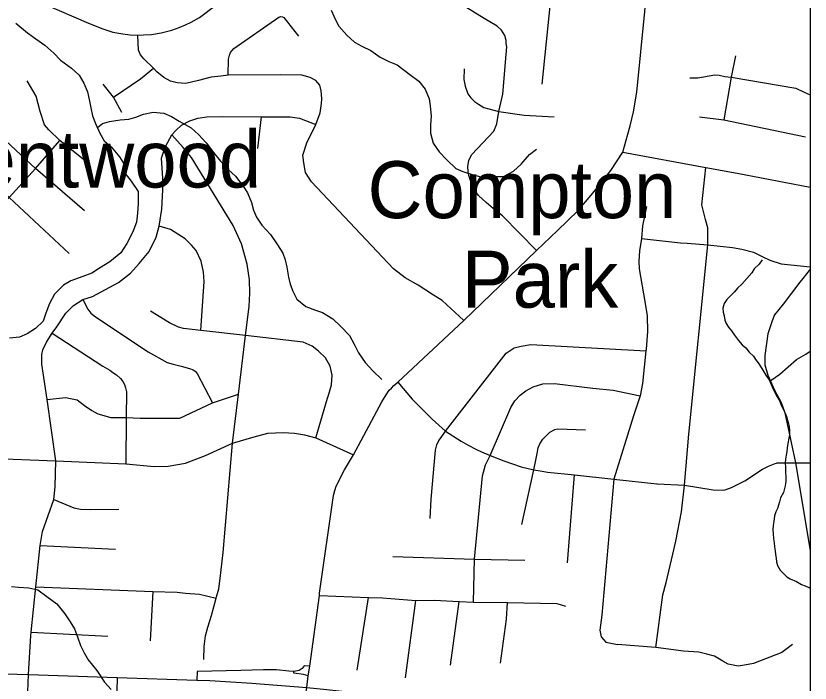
# Model space of a CAD drawing. Extents: x 0 to 69.5, y -4.5 to 22.
# Drawn here: x 7.698 to 8.8, y 15.277 to 16.203 of the extents above; entities that cross this region are included whole.
import ezdxf

# ---------------------------------------------------------------- set-up
doc = ezdxf.new("R2010")
doc.units = 0
for name, color, linetype in [('GM_X_County_Road', 7, 'Continuous'), ('GM_X_Interchange_Ramps', 7, 'Continuous'), ('GM_X_Minor_River', 7, 'Continuous'), ('GM_X_State_Route', 7, 'Continuous'), ('GM_X_Township_Subdivision', 7, 'Continuous'), ('GM_X_Unincorporated_Text', 7, 'Continuous'), ('SH_Data', 7, 'Continuous')]:
    doc.layers.add(name, color=color, linetype=linetype)

msp = doc.modelspace()

# ---------------------------------------------------------------- linework, layer by layer
at = {"layer": 'GM_X_County_Road'}
for points in [[(8.54, 16.0139), (8.547, 16.039), (8.5505, 16.0505), (8.5551, 16.0697), (8.5597, 16.0973), (8.5763, 16.2655), (8.5957, 16.4605), (8.6116, 16.6291), (8.6107, 16.6398), (8.609, 16.6494), (8.6074, 16.6579), (8.6047, 16.6681), (8.6008, 16.6786), (8.5656, 16.7531)], [(7.7409, 16.218), (7.7987, 16.1928), (7.8185, 16.1851), (7.8325, 16.1805), (7.8462, 16.178), (7.8564, 16.1767), (7.867, 16.1764), (7.8751, 16.1766), (7.8859, 16.1772), (7.8996, 16.1794), (7.9141, 16.1833), (7.9246, 16.1868), (7.9333, 16.1905), (7.9412, 16.1943), (7.9527, 16.2007), (7.9755, 16.2178)], [(8.2189, 15.6864), (8.2225, 15.69), (8.2279, 15.695), (8.3197, 15.7805), (8.4203, 15.8773), (8.4495, 15.9051), (8.4775, 15.9324), (8.4964, 15.9543), (8.5106, 15.972), (8.5233, 15.9886), (8.54, 16.0139)], [(8.54, 16.0139), (8.6554, 15.9928), (8.6988, 15.985), (8.8, 15.9653)], [(8.1194, 15.402), (8.1388, 15.5375), (8.1403, 15.5447), (8.1424, 15.5507), (8.1538, 15.573), (8.1663, 15.5941), (8.2056, 15.6677), (8.2115, 15.6772), (8.2161, 15.6837), (8.2189, 15.6864)], [(8.0892, 15.1724), (8.0893, 15.1794), (8.0906, 15.2033), (8.0943, 15.2247), (8.1014, 15.2712), (8.1035, 15.2873), (8.1057, 15.3008), (8.119, 15.3989), (8.1194, 15.402)]]:
    msp.add_lwpolyline(points, dxfattribs=at)
at = {"layer": 'GM_X_Interchange_Ramps'}
for points in [[(8.1057, 15.3008), (8.0981, 15.3011), (8.095, 15.2975), (8.0909, 15.295), (8.0836, 15.2933), (8.0767, 15.2941), (8.0595, 15.2956), (8.0416, 15.2956), (8.01, 15.2948), (7.9495, 15.2935), (7.9488, 15.2816)], [(8.1035, 15.2873), (8.0968, 15.2891), (8.0834, 15.2912), (8.0836, 15.2933)], [(7.8384, 15.2853), (7.8379, 15.2661), (7.8559, 15.2647), (7.8926, 15.2565), (8.0725, 15.212), (8.076, 15.2105), (8.0783, 15.2085), (8.0807, 15.2042), (8.0906, 15.2033)]]:
    msp.add_lwpolyline(points, dxfattribs=at)
at = {"layer": 'GM_X_Minor_River'}
for points in [[(8.1352, 16.2109), (8.141, 16.1986), (8.1461, 16.1889), (8.1571, 16.1761), (8.1676, 16.1667), (8.1781, 16.1611), (8.1904, 16.1548), (8.2035, 16.1457), (8.2155, 16.1397), (8.2268, 16.1349), (8.2444, 16.1215), (8.2571, 16.1124), (8.2659, 16.1012), (8.2713, 16.0881), (8.2729, 16.0782), (8.2741, 16.0637), (8.2734, 16.0519), (8.2732, 16.0405), (8.277, 16.0264), (8.2854, 16.0144), (8.2958, 16.0031), (8.3084, 15.9914), (8.3182, 15.987), (8.331, 15.9828), (8.3431, 15.9799), (8.353, 15.9793), (8.3648, 15.9801), (8.3747, 15.9802), (8.3885, 15.9875), (8.399, 15.9971), (8.4108, 16.0106), (8.4204, 16.0183)], [(7.6977, 16.193), (7.7141, 16.1797), (7.7257, 16.171), (7.738, 16.1624), (7.7507, 16.1514), (7.76, 16.1417), (7.7749, 16.1307), (7.7857, 16.1209), (7.7922, 16.1097), (7.7973, 16.0978), (7.7997, 16.0871), (7.8017, 16.0756), (7.804, 16.0642), (7.8084, 16.0538), (7.8145, 16.0403), (7.8203, 16.0299), (7.83, 16.0213), (7.8418, 16.0073), (7.8484, 15.9965), (7.8496, 15.9843), (7.8577, 15.9739), (7.8676, 15.9595), (7.8676, 15.9428), (7.8665, 15.9291), (7.8651, 15.917), (7.8602, 15.9034), (7.8518, 15.8873), (7.8435, 15.8742), (7.8284, 15.8616), (7.8137, 15.8532), (7.8033, 15.8459), (7.7907, 15.8416), (7.7742, 15.8355), (7.7638, 15.8293), (7.7513, 15.8171), (7.7445, 15.8039), (7.7396, 15.7908), (7.7356, 15.7794), (7.7251, 15.7694), (7.7135, 15.7621), (7.7031, 15.7574), (7.689, 15.7559)], [(7.811, 16.0481), (7.8179, 16.0536), (7.8278, 16.0564), (7.8427, 16.0587), (7.8545, 16.0599), (7.8644, 16.0627), (7.8752, 16.0666), (7.8885, 16.0693), (7.903, 16.0682), (7.9139, 16.0634), (7.9247, 16.057), (7.9412, 16.0475), (7.9512, 16.0385), (7.962, 16.0268), (7.9719, 16.0133), (7.9819, 16.0016), (7.9926, 15.99), (8.0027, 15.9806), (8.0133, 15.967), (8.0192, 15.9574), (8.0249, 15.9439), (8.0274, 15.9336), (8.0317, 15.9236), (8.039, 15.9128), (8.0512, 15.8995), (8.0611, 15.8852), (8.0685, 15.874), (8.0717, 15.8644), (8.0737, 15.8545), (8.0764, 15.8407), (8.0784, 15.8308), (8.0824, 15.8212), (8.0878, 15.81), (8.1001, 15.7998), (8.1137, 15.7949), (8.1234, 15.7913), (8.1377, 15.7826), (8.1488, 15.772), (8.1607, 15.7596), (8.1672, 15.7476), (8.1734, 15.7357), (8.1826, 15.7221), (8.1933, 15.7105), (8.2059, 15.6987)], [(8.7335, 15.8644), (8.7291, 15.8585), (8.7225, 15.8522), (8.7193, 15.8466), (8.7122, 15.8388), (8.7052, 15.8306), (8.6993, 15.8254), (8.695, 15.8202), (8.6907, 15.8158), (8.6844, 15.8095), (8.6809, 15.8038), (8.6788, 15.7974), (8.6794, 15.7921), (8.6808, 15.7867), (8.6818, 15.781), (8.6835, 15.7764), (8.6868, 15.7713), (8.6909, 15.7659), (8.6949, 15.76), (8.7004, 15.7527), (8.7059, 15.7468), (8.7108, 15.7425), (8.7152, 15.7366), (8.7215, 15.7311), (8.7244, 15.7265), (8.7281, 15.7218), (8.7328, 15.7137), (8.7386, 15.7047), (8.743, 15.6981), (8.7473, 15.6885), (8.7516, 15.6796), (8.7542, 15.6746), (8.7575, 15.6696), (8.7592, 15.6642), (8.7625, 15.6576), (8.7653, 15.6518), (8.7671, 15.6472), (8.7696, 15.6388), (8.7709, 15.6334), (8.7715, 15.6273), (8.7714, 15.622), (8.7705, 15.617), (8.7691, 15.6098), (8.7682, 15.6038), (8.7677, 15.5988), (8.7668, 15.5935), (8.7659, 15.5882), (8.7654, 15.5825), (8.766, 15.5768), (8.7658, 15.5707), (8.7663, 15.5627), (8.7662, 15.5574), (8.7656, 15.5509), (8.7631, 15.5418), (8.7591, 15.5343), (8.7574, 15.529), (8.7549, 15.5196), (8.7525, 15.5151), (8.7504, 15.5094), (8.7495, 15.5015), (8.7486, 15.4962), (8.7484, 15.4901), (8.7486, 15.4851), (8.7492, 15.4775), (8.7502, 15.4721), (8.7504, 15.4664), (8.7514, 15.461), (8.752, 15.4557), (8.7527, 15.4507), (8.7533, 15.4454), (8.7547, 15.4404), (8.7583, 15.4338), (8.7679, 15.4248), (8.7724, 15.422), (8.7811, 15.4183), (8.7882, 15.4143), (8.7931, 15.4123), (8.7983, 15.4098), (8.8, 15.4089)], [(8.7432, 15.6977), (8.7459, 15.6977), (8.7579, 15.7058), (8.7695, 15.7162), (8.7812, 15.7261), (8.7939, 15.7338), (8.8, 15.7377)], [(7.6916, 15.4112), (7.7015, 15.4106), (7.7159, 15.4095), (7.7284, 15.4065), (7.7407, 15.3975), (7.7549, 15.3872), (7.766, 15.3736), (7.7733, 15.3621), (7.7791, 15.3524), (7.7834, 15.3413), (7.7877, 15.3294), (7.7928, 15.3194), (7.7982, 15.3097), (7.81, 15.2946), (7.821, 15.2784), (7.8303, 15.2686)]]:
    msp.add_lwpolyline(points, dxfattribs=at)
at = {"layer": 'GM_X_State_Route'}
msp.add_lwpolyline([(7.375, 15.3384), (7.3915, 15.3291), (7.4204, 15.3166), (7.4471, 15.3074), (7.4931, 15.2985), (7.5414, 15.2945), (7.7154, 15.2893), (7.8384, 15.2853), (7.9488, 15.2816), (7.9669, 15.2811), (8.0254, 15.2774), (8.1014, 15.2712), (8.1295, 15.2684), (8.2078, 15.2595), (8.2788, 15.2497), (8.3376, 15.2408), (8.412, 15.227), (8.4869, 15.2128), (8.558, 15.1957), (8.6387, 15.1753)], dxfattribs=at)
at = {"layer": 'GM_X_Township_Subdivision'}
for points in [[(8.4505, 16.3018), (8.4455, 16.283), (8.4443, 16.2728), (8.4414, 16.2444), (8.4278, 16.1081)], [(8.4203, 15.8773), (8.3733, 15.9257), (8.3601, 15.9359), (8.3507, 15.9439), (8.34, 15.9538), (8.3354, 15.9605), (8.331, 15.9685), (8.3286, 15.9745), (8.3262, 15.9818), (8.3254, 15.9873), (8.3251, 15.9939), (8.3264, 16.003), (8.3307, 16.0109), (8.3611, 16.043), (8.3654, 16.0533), (8.3679, 16.0703), (8.3735, 16.0943), (8.3783, 16.1496), (8.3792, 16.1599), (8.3783, 16.1649), (8.378, 16.1691), (8.3762, 16.1756), (8.3719, 16.1832), (8.3657, 16.189), (8.3479, 16.1995), (8.2811, 16.2409)], [(7.9926, 16.1206), (7.9927, 16.1432), (7.9944, 16.1484), (7.9958, 16.1523), (8.0003, 16.1579), (8.0627, 16.2013), (8.0657, 16.202), (8.0678, 16.2016), (8.0695, 16.2008), (8.0901, 16.1751)], [(8.3197, 15.7805), (8.2892, 15.808), (8.2775, 15.8157), (8.2561, 15.8292), (8.2383, 15.8397), (8.2221, 15.852), (8.108, 15.9728), (8.0997, 15.9858), (8.0975, 15.9993), (8.0963, 16.0098), (8.1014, 16.0269), (8.1142, 16.0523), (8.1199, 16.0686), (8.1219, 16.0813), (8.1223, 16.088), (8.1221, 16.0939), (8.1215, 16.0992), (8.1197, 16.107), (8.1143, 16.1134), (8.1063, 16.1177), (8.0948, 16.1209), (8.0656, 16.1211), (7.9926, 16.1206), (7.9824, 16.1195), (7.9691, 16.1179), (7.9515, 16.1136), (7.9335, 16.1094), (7.9216, 16.1102), (7.9125, 16.1126), (7.9032, 16.1175), (7.8934, 16.1256), (7.8888, 16.1304), (7.8756, 16.1435), (7.8706, 16.149), (7.8681, 16.1556), (7.867, 16.1764)], [(7.7932, 15.9326), (7.7253, 15.9911), (7.6771, 16.036), (7.6695, 16.0455), (7.6608, 16.0579), (7.6529, 16.0736), (7.6476, 16.0883), (7.6459, 16.1058), (7.6452, 16.1249), (7.6467, 16.1474), (7.6477, 16.157), (7.6411, 16.1581), (7.6234, 16.1597)], [(8.6964, 16.1478), (8.6906, 16.1178), (8.6802, 16.0586)], [(7.8333, 16.0902), (7.8706, 16.1157), (7.8888, 16.1304)], [(8.3198, 16.1296), (8.3197, 16.1146), (8.3212, 16.1054), (8.3251, 16.0951), (8.3291, 16.0893), (8.3345, 16.0844), (8.3398, 16.0805), (8.3473, 16.0759), (8.3679, 16.0703), (8.4032, 16.0654), (8.4447, 16.0631)], [(8.633, 16.117), (8.6442, 16.1173), (8.6679, 16.1214), (8.6737, 16.1209), (8.6818, 16.1191), (8.6906, 16.1178), (8.7801, 16.1027), (8.7916, 16.0974), (8.8, 16.0936)], [(7.7917, 16.004), (7.7588, 16.0303), (7.7436, 16.0448), (7.7378, 16.0519), (7.7318, 16.0706), (7.726, 16.0916), (7.7135, 16.1127)], [(7.845, 16.0692), (7.8333, 16.0902), (7.8189, 16.1081)], [(7.7187, 15.3435), (7.719, 15.3478), (7.7256, 15.4109), (7.7315, 15.4683), (7.7346, 15.4877), (7.7506, 15.5319), (7.7524, 15.5498), (7.7531, 15.5855), (7.7411, 15.6709), (7.7337, 15.7197), (7.734, 15.7278), (7.7341, 15.7333), (7.7353, 15.7396), (7.7403, 15.7502), (7.7483, 15.7628), (7.7547, 15.7715), (7.7671, 15.7908), (7.7779, 15.8013), (7.791, 15.8094), (7.8041, 15.8135), (7.8402, 15.8333), (7.8571, 15.8461), (7.8691, 15.8595), (7.8828, 15.8761), (7.8927, 15.8962), (7.8967, 15.9111), (7.9006, 15.9348), (7.9022, 15.9711), (7.8999, 16.0058), (7.9055, 16.0219), (7.9141, 16.0379), (7.92, 16.0442), (7.9279, 16.0515), (7.9391, 16.0575), (7.9502, 16.0612), (7.9629, 16.0632), (7.9848, 16.0636), (8.0385, 16.063), (8.0699, 16.0632), (8.0787, 16.063), (8.0914, 16.0611), (8.1142, 16.0523)], [(8.0334, 16.0189), (8.0385, 16.063)], [(8.6466, 16.0628), (8.6802, 16.0586), (8.7934, 16.0354)], [(7.9762, 15.397), (7.9796, 15.4079), (7.9814, 15.4225), (7.9857, 15.4585), (7.9983, 15.6101), (8.0067, 15.6783), (8.0167, 15.7595), (8.0217, 15.7998), (8.0226, 15.8181), (8.0221, 15.837), (8.0189, 15.8587), (8.0108, 15.8869), (7.9993, 15.9121), (7.9415, 16.0066), (7.9299, 16.0204), (7.9141, 16.0379)], [(7.6489, 15.9085), (7.6888, 15.9511), (7.7253, 15.9911), (7.7588, 16.0303)], [(8.5857, 15.3269), (8.5958, 15.3998), (8.6004, 15.4168), (8.6095, 15.4562), (8.6135, 15.4741), (8.6213, 15.5151), (8.6259, 15.552), (8.6319, 15.6225), (8.658, 15.8854), (8.6582, 15.8987), (8.6582, 15.9088), (8.6547, 15.9207), (8.6519, 15.9315), (8.6498, 15.941), (8.6554, 15.9928)], [(7.7717, 15.8732), (7.6888, 15.9511), (7.6405, 15.9885)], [(8.5728, 15.9384), (8.5674, 15.9119), (8.5662, 15.8942), (8.5634, 15.877), (8.5625, 15.8629), (8.5627, 15.8519), (8.5707, 15.8068), (8.574, 15.787), (8.5742, 15.765), (8.5724, 15.7407), (8.5721, 15.7385), (8.5672, 15.6929), (8.5642, 15.6759), (8.5549, 15.6483), (8.5274, 15.5602), (8.5111, 15.3715), (8.5084, 15.3507), (8.51, 15.3414), (8.5166, 15.3342), (8.5329, 15.331)], [(7.9545, 15.7666), (7.9591, 15.8343), (7.9584, 15.8476), (7.9552, 15.8628), (7.9481, 15.8773), (7.9418, 15.885), (7.9327, 15.8935), (7.9125, 15.9066), (7.8967, 15.9111)], [(8.5662, 15.8942), (8.62, 15.8882), (8.6293, 15.8875)], [(8.6293, 15.8875), (8.658, 15.8854), (8.6922, 15.8815), (8.7054, 15.8793), (8.7215, 15.875), (8.7336, 15.869), (8.744, 15.8642), (8.7599, 15.8588), (8.8, 15.8547)], [(8.8, 15.8515), (8.7897, 15.8388)], [(8.7897, 15.8388), (8.7858, 15.8338), (8.7625, 15.803), (8.7504, 15.7884), (8.7474, 15.78), (8.7412, 15.7619), (8.7371, 15.7318), (8.7372, 15.719), (8.7414, 15.7045), (8.7504, 15.6838), (8.7599, 15.6668), (8.7649, 15.6522), (8.7799, 15.5828), (8.8, 15.4615)], [(7.791, 15.8094), (7.7977, 15.796), (7.8021, 15.7905), (7.8083, 15.7857), (7.8814, 15.7371), (7.9078, 15.722), (7.9161, 15.7197), (7.9271, 15.7169), (7.9388, 15.7137), (7.9437, 15.7118), (7.9466, 15.71), (7.9494, 15.7068), (7.9706, 15.6663)], [(8.1141, 15.6178), (8.1303, 15.6727), (8.1323, 15.6782), (8.1359, 15.6911), (8.1368, 15.7044), (8.1342, 15.717), (8.1275, 15.7284), (8.1178, 15.738), (8.1091, 15.7446), (8.0967, 15.7504), (8.0167, 15.7595), (7.9545, 15.7666), (7.9307, 15.7693), (7.9235, 15.7713), (7.911, 15.7771), (7.8847, 15.7933)], [(7.7483, 15.7628), (7.8187, 15.7171), (7.8282, 15.7114), (7.8324, 15.7084), (7.8374, 15.7048), (7.8429, 15.6998), (7.8461, 15.696), (7.8485, 15.6917), (7.8499, 15.687), (7.8514, 15.6813), (7.8511, 15.6456), (7.8505, 15.5815)], [(8.2727, 15.5057), (8.2742, 15.5325), (8.28, 15.6007), (8.2822, 15.6077), (8.2849, 15.6138), (8.2882, 15.6181), (8.2942, 15.6268), (8.3784, 15.7352), (8.3891, 15.7423), (8.399, 15.7449), (8.4126, 15.747), (8.5721, 15.7385)], [(8.2279, 15.695), (8.2476, 15.6713), (8.2757, 15.6437), (8.2942, 15.6268), (8.316, 15.6128), (8.3257, 15.6076), (8.336, 15.602), (8.344, 15.598), (8.3559, 15.5933), (8.3751, 15.5855), (8.3991, 15.5775), (8.4165, 15.5732), (8.4283, 15.5713), (8.4355, 15.5702), (8.4731, 15.5661), (8.5274, 15.5602), (8.5875, 15.5537), (8.5884, 15.5537)], [(8.333, 15.3895), (8.3345, 15.4494), (8.3454, 15.5649), (8.3496, 15.58), (8.3559, 15.5933), (8.3846, 15.6595), (8.3903, 15.6689), (8.3977, 15.6767), (8.4057, 15.683), (8.4157, 15.6882), (8.4293, 15.6925), (8.4454, 15.6929), (8.4985, 15.6867), (8.5269, 15.6838), (8.5642, 15.6759)], [(7.7411, 15.6709), (7.7666, 15.6735), (7.7827, 15.6702), (7.7931, 15.6626), (7.8033, 15.6556), (7.8116, 15.6511), (7.8297, 15.6456), (7.8511, 15.6456), (7.8705, 15.6449), (7.9256, 15.6448), (7.9706, 15.6663), (8.0067, 15.6783)], [(8.3998, 15.4972), (8.4165, 15.5732), (8.4194, 15.5865), (8.4212, 15.5959), (8.4228, 15.6036), (8.4251, 15.6092), (8.4291, 15.6159), (8.4331, 15.6201), (8.4361, 15.6228), (8.439, 15.6255), (8.4458, 15.629), (8.45, 15.6303), (8.4884, 15.6285)], [(7.6247, 15.5879), (7.6581, 15.5895), (7.7531, 15.5855), (7.8505, 15.5815), (7.89, 15.5779), (7.9094, 15.5785), (7.9333, 15.5824), (7.9612, 15.593), (7.9983, 15.6101), (8.0287, 15.619), (8.0475, 15.6239), (8.069, 15.6248), (8.0844, 15.6239), (8.0983, 15.6218), (8.1141, 15.6178), (8.1663, 15.5941)], [(8.5884, 15.5537), (8.6259, 15.552), (8.6655, 15.5453), (8.6791, 15.5451), (8.6821, 15.5456), (8.6909, 15.5488), (8.7096, 15.5581), (8.7337, 15.5742), (8.7424, 15.5783), (8.7515, 15.5819), (8.7535, 15.5825), (8.7545, 15.5827), (8.7554, 15.5827), (8.7799, 15.5828), (8.8, 15.583)], [(8.4634, 15.4441), (8.4731, 15.5661)], [(7.7506, 15.5319), (7.7783, 15.5206), (7.7877, 15.5186), (7.801, 15.5181), (7.8408, 15.5188)], [(7.7315, 15.4683), (7.8361, 15.463)], [(8.221, 15.453), (8.3345, 15.4494), (8.4042, 15.4478)], [(7.7256, 15.4109), (7.8879, 15.4043), (7.9216, 15.4033), (7.9334, 15.4023), (7.9529, 15.4005), (7.9757, 15.3951)], [(7.8879, 15.4043), (7.8843, 15.3361)], [(7.9587, 15.31), (7.9591, 15.3281), (7.9612, 15.3428), (7.9641, 15.3548), (7.9695, 15.3711), (7.9757, 15.3951), (7.9762, 15.397)], [(8.119, 15.3989), (8.1871, 15.3959), (8.2065, 15.3958), (8.2527, 15.3919), (8.2781, 15.3926), (8.3132, 15.3906), (8.333, 15.3895), (8.38, 15.389), (8.4484, 15.3877), (8.4605, 15.3842)], [(8.1713, 15.2951), (8.1871, 15.3959)], [(8.2385, 15.2848), (8.2527, 15.3919)], [(8.3008, 15.302), (8.3132, 15.3906)], [(8.3704, 15.305), (8.3786, 15.3659), (8.38, 15.389)], [(7.7139, 15.2531), (7.7154, 15.2893), (7.7187, 15.3435)], [(7.719, 15.3478), (7.8257, 15.3423)], [(8.7754, 15.3307), (8.7608, 15.3198), (8.7215, 15.3044), (8.709, 15.3024), (8.7, 15.3009), (8.6864, 15.3038), (8.679, 15.3077), (8.6672, 15.3148), (8.6567, 15.3173), (8.6455, 15.3203), (8.6244, 15.3215), (8.5857, 15.3269), (8.5329, 15.331)]]:
    msp.add_lwpolyline(points, dxfattribs=at)
at = {"layer": 'SH_Data'}
msp.add_line((8.8, 21), (8.8, 14.2), dxfattribs=at)

# ---------------------------------------------------------------- texts
at = {"layer": 'GM_X_Unincorporated_Text'}
for s, p in [('Brentwood', (7.5334, 15.9649)), ('Compton', (8.1859, 15.9224)), ('Park', (8.3167, 15.7982))]:
    msp.add_text(s, height=0.07898, rotation=0, dxfattribs=at).set_placement(p)

doc.saveas('drawing.dxf')
